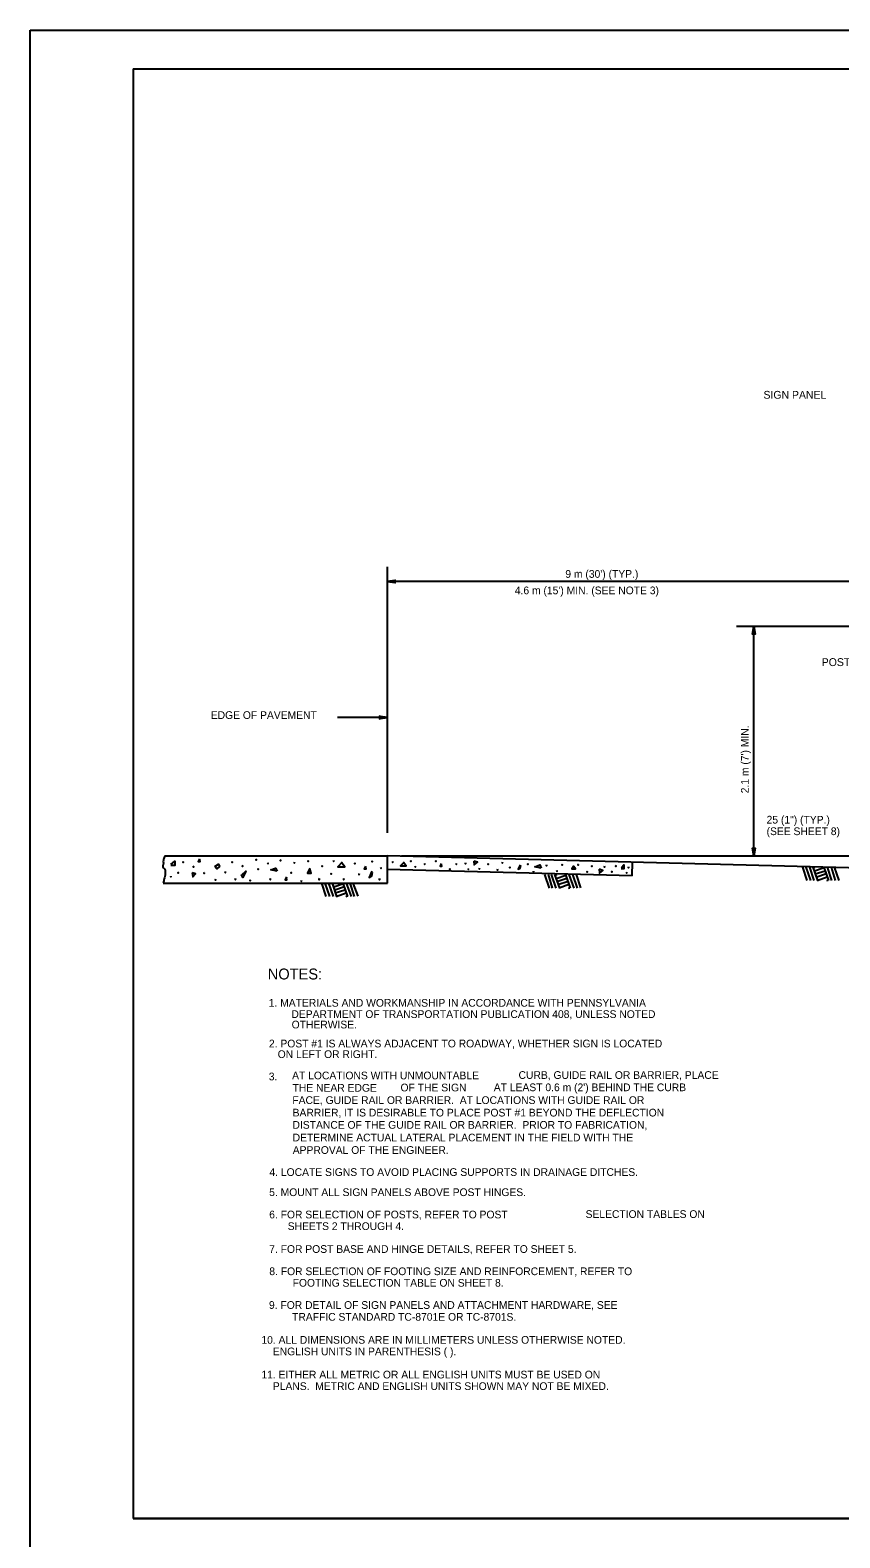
# Model space of a CAD drawing. Extents: x 637580 to 641008, y 294594 to 295782.
# Drawn here: x 637580 to 637895, y 295195 to 295782 of the extents above; entities that cross this region are included whole.
import ezdxf

# ---------------------------------------------------------------- set-up
doc = ezdxf.new("R2010")
doc.units = 0
for name, color, linetype in [('1', 7, 'Continuous'), ('2', 7, 'Continuous'), ('3', 7, 'Continuous'), ('PLT-BNDY', 7, 'Continuous')]:
    doc.layers.add(name, color=color, linetype=linetype)

# ---------------------------------------------------------------- blocks, each defined once
blk = doc.blocks.new('RARROW')
at = {"layer": '3'}
blk.add_lwpolyline([(-2.2695, 0.285), (-2.184875, 0.12075), (0, 0), (-2.2695, 0.285), (-2.38575, 0.384625), (0, 0), (-2.183125, -0.108), (-2.262875, -0.2705), (0, 0), (-2.38575, -0.379125), (-2.262875, -0.2705)], dxfattribs=at)

msp = doc.modelspace()

# ---------------------------------------------------------------- linework, layer by layer
at = {"layer": '1'}
for p, q in [((637620.31, 295766.63), (638406.31, 295766.63)), ((637620.31, 295766.63), (637620.31, 295202.63)), ((637880.56, 295456), (637882.31, 295450.88)), ((637881.94, 295456), (637883.69, 295450.88)), ((637883.31, 295456), (637885.06, 295450.88)), ((637884.56, 295456), (637886.44, 295450.88)), ((637884.69, 295455.63), (637885.44, 295456)), ((637885.06, 295454.5), (637888.94, 295455.88)), ((637888.94, 295456), (637890.69, 295450.88)), ((637890.19, 295456), (637891.94, 295450.88)), ((637891.69, 295456), (637893.31, 295450.88)), ((637892.94, 295456), (637894.69, 295450.88)), ((637693.56, 295449.75), (637695.31, 295444.63)), ((637694.94, 295449.75), (637696.69, 295444.63)), ((637696.31, 295449.75), (637698.06, 295444.63)), ((637697.69, 295449.5), (637698.31, 295449.75)), ((637697.69, 295449.75), (637699.44, 295444.63)), ((637698.06, 295448.25), (637702.06, 295449.63)), ((637701.94, 295449.75), (637703.69, 295444.63)), ((637703.19, 295449.75), (637705.06, 295444.63)), ((637704.56, 295449.75), (637706.31, 295444.63)), ((637705.81, 295449.75), (637707.69, 295444.75)), ((637780.31, 295453.13), (637782.06, 295447.88)), ((637781.69, 295453.13), (637783.31, 295447.88)), ((637782.94, 295453.13), (637784.69, 295447.88)), ((637784.19, 295453.13), (637786.06, 295447.88)), ((637784.31, 295452.88), (637785.06, 295453.13)), ((637784.81, 295451.63), (637788.56, 295452.88)), ((637785.06, 295450.5), (637788.94, 295451.75)), ((637785.44, 295449.25), (637789.44, 295450.63)), ((637788.44, 295453.13), (637790.31, 295447.88)), ((637789.81, 295453.13), (637791.69, 295447.88)), ((637791.19, 295453.13), (637792.94, 295447.88)), ((637792.56, 295453.13), (637794.31, 295448)), ((637885.56, 295453.38), (637889.44, 295454.63)), ((637885.94, 295452.13), (637889.81, 295453.5)), ((637886.31, 295450.88), (637890.19, 295452.25)), ((637890.06, 295450.88), (637890.56, 295451)), ((637698.56, 295447.13), (637702.44, 295448.5)), ((637698.94, 295446), (637702.69, 295447.25)), ((637699.31, 295444.63), (637703.19, 295446)), ((637703.06, 295444.63), (637703.69, 295444.88)), ((637785.94, 295448), (637789.81, 295449.38)), ((637789.56, 295447.88), (637790.19, 295448)), ((638406.31, 295202.63), (637620.31, 295202.63)), ((637620.31, 295202.63), (638206.31, 295202.63))]:
    msp.add_line(p, q, dxfattribs=at)
at = {"layer": '2'}
for p, q in [((637719.19, 295469.38), (637719.19, 295572.88)), ((637909.44, 295567.13), (637719.19, 295567.13)), ((637900.19, 295549.63), (637854.94, 295549.63)), ((637861.69, 295460.38), (637861.69, 295549.63)), ((637719.19, 295514.25), (637699.87, 295514.25)), ((637632.69, 295460.38), (637719.19, 295460.38)), ((637909.44, 295455.5), (637719.19, 295460.38)), ((637719.19, 295449.75), (637719.19, 295460.38)), ((637724.69, 295460.38), (638231.69, 295460.38)), ((637814.31, 295452.63), (637814.44, 295458)), ((637632.06, 295449.75), (637719.19, 295449.75)), ((637814.31, 295452.63), (637719.06, 295455.13))]:
    msp.add_line(p, q, dxfattribs=at)
for points in [[(637635.06, 295457), (637636.56, 295458.38), (637636.56, 295456.63), (637634.94, 295456.63)], [(637639.81, 295458.25), (637639.69, 295458), (637639.94, 295458), (637639.81, 295458.25)], [(637643.69, 295456.38), (637643.69, 295456.13), (637643.94, 295456.13), (637643.69, 295456.38)], [(637646.19, 295459.25), (637645.69, 295458.25), (637646.44, 295458.25), (637646.19, 295459.13)], [(637652.06, 295456.25), (637653.56, 295457.25), (637653.94, 295456.25), (637652.94, 295455.38), (637652.06, 295456.25)], [(637658.81, 295458.25), (637658.69, 295458), (637658.94, 295458), (637658.81, 295458.25)], [(637662.94, 295456.63), (637662.69, 295456.38), (637662.94, 295456.38), (637662.94, 295456.63)], [(637668.31, 295459.13), (637668.06, 295458.88), (637668.31, 295458.88), (637668.31, 295459.13)], [(637668.94, 295455.38), (637668.81, 295455.25), (637669.06, 295455.25), (637668.94, 295455.38)], [(637672.69, 295457.75), (637672.69, 295457.5), (637672.81, 295457.5), (637672.69, 295457.75)], [(637676.31, 295454.5), (637673.94, 295455), (637675.69, 295455.63), (637676.31, 295454.5)], [(637677.81, 295458.88), (637677.56, 295458.63), (637677.81, 295458.63), (637677.81, 295458.88)], [(637683.06, 295458), (637682.94, 295457.75), (637683.06, 295457.75), (637683.06, 295458)], [(637689.06, 295455.63), (637688.19, 295453.63), (637689.56, 295453.63), (637689.06, 295455.38)], [(637688.44, 295458.63), (637688.31, 295458.38), (637688.56, 295458.38), (637688.44, 295458.63)], [(637693.81, 295456.63), (637693.69, 295456.38), (637693.94, 295456.38), (637693.81, 295456.63)], [(637698.31, 295458.63), (637698.31, 295458.38), (637698.44, 295458.38), (637698.31, 295458.63)], [(637701.56, 295458), (637699.94, 295456.13), (637702.69, 295456.13), (637701.56, 295457.5)], [(637706.56, 295457.75), (637706.44, 295457.5), (637706.69, 295457.5), (637706.56, 295457.75)], [(637710.69, 295456.38), (637710.19, 295455.38), (637710.94, 295455.38), (637710.69, 295456.25)], [(637713.31, 295458.38), (637713.19, 295458.25), (637713.44, 295458.25), (637713.31, 295458.38)], [(637716.69, 295455.88), (637716.69, 295455.63), (637716.81, 295455.63), (637716.69, 295455.88)], [(637721.31, 295458.25), (637721.19, 295458), (637721.31, 295458), (637721.31, 295458.25)], [(637725.69, 295458), (637724.31, 295456.5), (637726.56, 295456.5), (637725.69, 295457.5)], [(637728.31, 295458.63), (637728.19, 295458.38), (637728.44, 295458.38), (637728.31, 295458.63)], [(637730.06, 295456.38), (637730.06, 295456.13), (637730.19, 295456.13), (637730.06, 295456.38)], [(637733.81, 295457.5), (637733.69, 295457.25), (637733.81, 295457.25), (637733.81, 295457.5)], [(637738.06, 295458.63), (637737.94, 295458.38), (637738.19, 295458.38), (637738.06, 295458.63)], [(637740.06, 295457.5), (637739.69, 295456.38), (637740.31, 295456.38), (637740.06, 295457.25)], [(637743.44, 295455.38), (637743.31, 295455.25), (637743.56, 295455.25), (637743.44, 295455.38)], [(637745.94, 295457.5), (637745.94, 295457.25), (637746.06, 295457.25), (637745.94, 295457.5)], [(637749.56, 295457.75), (637749.44, 295457.5), (637749.69, 295457.5), (637749.56, 295457.75)], [(637750.69, 295455.38), (637750.56, 295455.25), (637750.69, 295455.25), (637750.69, 295455.38)], [(637752.81, 295458.38), (637752.94, 295456.88), (637754.19, 295458), (637752.81, 295458.38)], [(637755.06, 295455.63), (637754.94, 295455.38), (637755.06, 295455.38), (637755.06, 295455.63)], [(637758.44, 295457.5), (637758.31, 295457.25), (637758.56, 295457.25), (637758.44, 295457.5)], [(637763.94, 295458), (637763.81, 295457.75), (637763.94, 295457.75), (637763.94, 295458)], [(637766.81, 295456.13), (637766.69, 295455.88), (637766.94, 295455.88), (637766.81, 295456.13)], [(637770.81, 295456.88), (637770.06, 295455.25), (637770.81, 295455.63), (637771.06, 295456.63)], [(637773.81, 295457.5), (637773.69, 295457.25), (637773.94, 295457.25), (637773.81, 295457.5)], [(637778.94, 295455.63), (637776.56, 295456.13), (637778.44, 295456.88), (637778.94, 295455.63)], [(637781.06, 295456.88), (637780.94, 295456.63), (637781.19, 295456.63), (637781.06, 295456.88)], [(637787.19, 295457), (637787.06, 295456.88), (637787.31, 295456.88), (637787.19, 295457)], [(637791.69, 295456.5), (637790.94, 295455.38), (637792.31, 295455.38), (637791.69, 295456.25)], [(637793.56, 295457), (637793.31, 295456.88), (637793.56, 295456.88), (637793.56, 295457)], [(637798.69, 295456.63), (637798.56, 295456.38), (637798.81, 295456.38), (637798.69, 295456.63)], [(637803.56, 295456.38), (637803.44, 295456.13), (637803.69, 295456.13), (637803.56, 295456.38)], [(637808.19, 295456.63), (637807.94, 295456.38), (637808.19, 295456.38), (637808.19, 295456.63)], [(637810.19, 295455.88), (637811.19, 295456.88), (637811.19, 295455.38), (637810.06, 295455.38)], [(637812.94, 295456.13), (637812.81, 295455.88), (637813.06, 295455.88), (637812.94, 295456.13)], [(637635.06, 295452.5), (637635.06, 295452.25), (637635.06, 295452.25), (637635.06, 295452.38)], [(637637.94, 295454.13), (637637.69, 295453.88), (637637.94, 295453.88), (637637.94, 295454)], [(637643.31, 295453.88), (637643.56, 295452.25), (637644.56, 295453.38), (637643.31, 295453.88)], [(637648.06, 295453.88), (637647.81, 295453.63), (637648.06, 295453.63), (637648.06, 295453.88)], [(637652.31, 295451.38), (637652.19, 295451.13), (637652.44, 295451.13), (637652.31, 295451.25)], [(637656.19, 295454.38), (637656.19, 295454), (637656.31, 295454), (637656.19, 295454.25)], [(637660.19, 295451.63), (637660.06, 295451.25), (637660.19, 295451.25), (637660.19, 295451.63)], [(637662.69, 295453.13), (637664.19, 295454.5), (637662.94, 295452), (637662.44, 295453.13)], [(637665.81, 295451.13), (637665.69, 295450.88), (637665.94, 295450.88), (637665.81, 295451)], [(637673.69, 295451.63), (637673.69, 295451.25), (637673.81, 295451.25), (637673.69, 295451.63)], [(637679.94, 295452.25), (637679.44, 295451.13), (637680.06, 295451.13), (637679.94, 295452.13)], [(637681.94, 295454.13), (637681.69, 295453.88), (637681.94, 295453.88), (637681.94, 295454)], [(637685.81, 295450.88), (637685.69, 295450.63), (637685.81, 295450.63), (637685.81, 295450.88)], [(637692.81, 295451.63), (637692.56, 295451.25), (637692.81, 295451.25), (637692.81, 295451.63)], [(637697.31, 295453.63), (637697.19, 295453.38), (637697.44, 295453.38), (637697.31, 295453.63)], [(637702.31, 295451.63), (637702.19, 295451.25), (637702.31, 295451.25), (637702.31, 295451.63)], [(637708.19, 295453.5), (637708.06, 295453.13), (637708.19, 295453.13), (637708.19, 295453.38)], [(637713.19, 295454.5), (637712.06, 295452), (637713.19, 295452.63), (637713.44, 295454.13)], [(637716.19, 295451.63), (637716.06, 295451.25), (637716.31, 295451.25), (637716.19, 295451.63)], [(637762.06, 295455.25), (637761.94, 295455), (637762.19, 295455), (637762.06, 295455.25)], [(637776.06, 295454.5), (637776.06, 295454.25), (637776.06, 295454.25), (637776.06, 295454.5)], [(637785.06, 295454.75), (637785.06, 295454.5), (637785.19, 295454.5), (637785.06, 295454.75)], [(637796.94, 295454.5), (637796.81, 295454.25), (637797.06, 295454.25), (637796.94, 295454.5)], [(637801.56, 295455.25), (637801.69, 295453.63), (637802.94, 295454.75), (637801.56, 295455.25)], [(637806.56, 295454.5), (637806.31, 295454.25), (637806.56, 295454.25), (637806.56, 295454.5)], [(637812.19, 295454.13), (637812.19, 295453.88), (637812.31, 295453.88), (637812.19, 295454)]]:
    msp.add_lwpolyline(points, dxfattribs=at)
msp.add_spline([(637632.69, 295460.38), (637632.19, 295459.13), (637632.06, 295458.25), (637632.06, 295457), (637631.94, 295456.13), (637632.56, 295455.38), (637632.81, 295454.25), (637632.81, 295452.88), (637632.31, 295451), (637632.06, 295449.75)], degree=3, dxfattribs=at)
at = {"layer": 'PLT-BNDY'}
msp.add_lwpolyline([(637580.31, 295781.63), (638421.31, 295781.63), (638421.31, 295187.63), (637580.31, 295187.63)], close=True, dxfattribs=at)

# ---------------------------------------------------------------- block references
at = {"layer": '2', "xscale": 1.2574347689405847, "yscale": 1.3092961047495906}
for p, rotation in [((637719.19, 295567.13), 180), ((637861.69, 295549.63), 89.99999999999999), ((637861.69, 295460.38), -90.00000000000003)]:
    msp.add_blockref('RARROW', p, dxfattribs=dict(at, rotation=rotation))
msp.add_blockref('RARROW', (637719.19, 295514.25), dxfattribs=at)

# ---------------------------------------------------------------- texts
at = {"layer": '1'}
for s, height, p in [('SIGN PANEL', 3.043, (637865.44, 295638.25)), ("9 m (30') (TYP.)", 3, (637788.38, 295568.59)), ("4.6 m (15') MIN. (SEE NOTE 3)", 3, (637768.74, 295562.19)), ('POST HINGE', 3.061, (637888.06, 295534.25)), ('1. MATERIALS AND WORKMANSHIP IN ACCORDANCE WITH PENNSYLVANIA', 3, (637673.06, 295401.75)), ('DEPARTMENT OF TRANSPORTATION PUBLICATION 408, UNLESS NOTED', 3, (637681.88, 295397.36)), ('OTHERWISE.', 3, (637681.98, 295393.3)), ('2. POST #1 IS ALWAYS ADJACENT TO ROADWAY, WHETHER SIGN IS LOCATED', 3, (637673.15, 295385.91)), ('   ON LEFT OR RIGHT.', 3, (637673.2, 295381.78)), ('3.', 3, (637673.08, 295373.1)), ('AT LOCATIONS WITH UNMOUNTABLE', 3, (637682.16, 295373.49)), (' CURB, GUIDE RAIL OR BARRIER, PLACE ', 3, (637769.09, 295373.66)), ('THE NEAR EDGE', 3, (637682.33, 295368.68)), ('OF THE SIGN ', 3, (637724.31, 295368.8)), ("AT LEAST 0.6 m (2') BEHIND THE CURB", 3, (637760.57, 295368.88)), ('FACE, GUIDE RAIL OR BARRIER.  AT LOCATIONS WITH GUIDE RAIL OR', 3, (637682.25, 295363.9)), ('BARRIER, IT IS DESIRABLE TO PLACE POST #1 BEYOND THE DEFLECTION ', 3, (637682.36, 295359.04)), ('DISTANCE OF THE GUIDE RAIL OR BARRIER.  PRIOR TO FABRICATION,', 3, (637682.3, 295354.27)), ('DETERMINE ACTUAL LATERAL PLACEMENT IN THE FIELD WITH THE', 3, (637682.36, 295349.35)), ('APPROVAL OF THE ENGINEER.', 3, (637682.41, 295344.49)), ('4. LOCATE SIGNS TO AVOID PLACING SUPPORTS IN DRAINAGE DITCHES.', 3, (637673.33, 295335.91)), ('5. MOUNT ALL SIGN PANELS ABOVE POST HINGES.', 3, (637673.24, 295328.08)), ('6. FOR SELECTION OF POSTS, REFER TO POST', 3, (637673.25, 295319.4)), ('SELECTION TABLES ON', 3, (637796.26, 295319.57)), (' SHEETS 2 THROUGH 4.', 3, (637679.33, 295314.87)), ('7. FOR POST BASE AND HINGE DETAILS, REFER TO SHEET 5.', 3, (637673.25, 295305.98)), ('8. FOR SELECTION OF FOOTING SIZE AND REINFORCEMENT, REFER TO', 3, (637673.29, 295297.32)), ('FOOTING SELECTION TABLE ON SHEET 8.', 3, (637682.37, 295292.83)), ('9. FOR DETAIL OF SIGN PANELS AND ATTACHMENT HARDWARE, SEE', 3, (637673.16, 295284.2)), ('TRAFFIC STANDARD TC-8701E OR TC-8701S.', 3, (637682.15, 295279.59))]:
    msp.add_text(s, height=height, dxfattribs=at).set_placement(p)
at = {"layer": '2'}
for s, height, p in [('NOTES:', 4.25, (637672.68, 295412.34)), ('10. ALL DIMENSIONS ARE IN MILLIMETERS UNLESS OTHERWISE NOTED.', 3, (637670.21, 295270.64)), ('    ENGLISH UNITS IN PARENTHESIS ( ).', 3, (637670.21, 295266.14)), ('11. EITHER ALL METRIC OR ALL ENGLISH UNITS MUST BE USED ON', 3, (637670.21, 295257.14)), ('    PLANS.  METRIC AND ENGLISH UNITS SHOWN MAY NOT BE MIXED.     ', 3, (637670.21, 295252.64))]:
    msp.add_text(s, height=height, dxfattribs=at).set_placement(p)
at = {"layer": '3'}
for s, p in [('EDGE OF PAVEMENT', (637650.53, 295513.68)), ('25 (1") (TYP.)', (637866.64, 295472.99)), ('(SEE SHEET 8)', (637866.64, 295468.49))]:
    msp.add_text(s, height=3, dxfattribs=at).set_placement(p)
msp.add_text("2.1 m (7') MIN.", height=3, rotation=90, dxfattribs=at).set_placement((637859.7, 295484.76))

doc.saveas('drawing.dxf')
